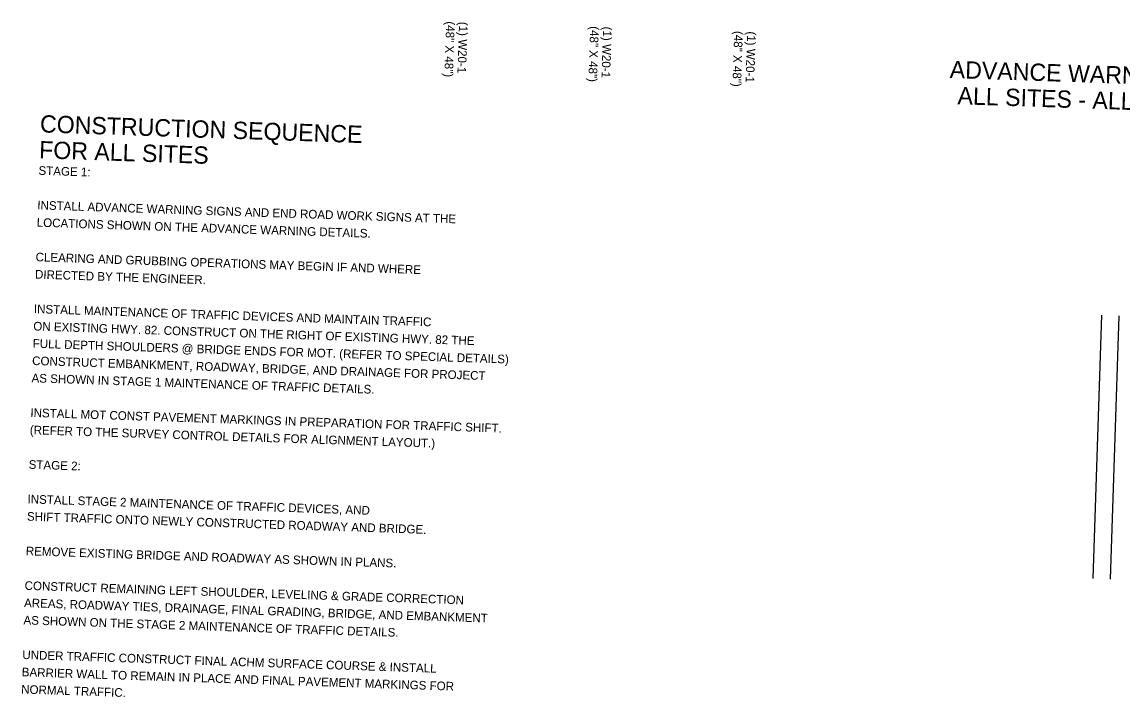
# Model space of a CAD drawing. Extents: x 977269 to 979191, y 1525946 to 1526973.
# Drawn here: x 977311 to 978075, y 1526026 to 1526494 of the extents above; entities that cross this region are included whole.
import ezdxf

# ---------------------------------------------------------------- set-up
doc = ezdxf.new("R2010")
doc.units = 0
doc.layers.add('R_Border', color=7, linetype='Continuous')
doc.layers.add('STAMP', color=7, linetype='Continuous')

msp = doc.modelspace()

# ---------------------------------------------------------------- linework, layer by layer
at = {"layer": 'STAMP'}
for p, q in [((978060.44, 1526290.78), (978054.35, 1526108.19)), ((978072.41, 1526290.39), (978066.32, 1526107.8))]:
    msp.add_line(p, q, dxfattribs=at)

# ---------------------------------------------------------------- texts
at = {"layer": 'R_Border'}
for s, height, rotation, p in [('(48" X 48")', 6, 268.09005, (977605.68, 1526494.7)), ('(1) W20-1', 6, 268.09005, (977614.68, 1526494.4)), ('(48" X 48")', 6, 268.09005, (977705.62, 1526491.37)), ('(1) W20-1', 6, 268.09005, (977714.62, 1526491.07)), ('(48" X 48")', 6, 268.09005, (977805.57, 1526488.04)), ('(1) W20-1', 6, 268.09005, (977814.56, 1526487.74)), ('ADVANCE WARNING DETAILS', 12, 358.09005, (977954.93, 1526455.38)), ('ALL SITES - ALL STAGES', 12, 358.09005, (977960.33, 1526437.19)), ('CONSTRUCTION SEQUENCE ', 12, 358.09005, (977323.76, 1526417.66)), ('FOR ALL SITES', 12, 358.09005, (977323.16, 1526399.67)), ('STAGE 1:', 6, 358.09005, (977322.78, 1526388.23)), ('INSTALL ADVANCE WARNING SIGNS AND END ROAD WORK SIGNS AT THE', 6, 358.09005, (977321.98, 1526364.25)), ('LOCATIONS SHOWN ON THE ADVANCE WARNING DETAILS.  ', 6, 358.09005, (977321.58, 1526352.25)), ('CLEARING AND GRUBBING OPERATIONS MAY BEGIN IF AND WHERE', 6, 358.09005, (977320.78, 1526328.27)), ('DIRECTED BY THE ENGINEER.', 6, 358.09005, (977320.38, 1526316.27)), ('INSTALL MAINTENANCE OF TRAFFIC DEVICES AND MAINTAIN TRAFFIC ', 6, 358.09005, (977319.58, 1526292.29)), ('ON EXISTING HWY. 82. CONSTRUCT ON THE RIGHT OF EXISTING HWY. 82 THE', 6, 358.09005, (977319.18, 1526280.29)), ('FULL DEPTH SHOULDERS @ BRIDGE ENDS FOR MOT. (REFER TO SPECIAL DETAILS)', 6, 358.09005, (977318.78, 1526268.3)), ('CONSTRUCT EMBANKMENT, ROADWAY, BRIDGE, AND DRAINAGE FOR PROJECT ', 6, 358.09005, (977318.38, 1526256.31)), ('AS SHOWN IN STAGE 1 MAINTENANCE OF TRAFFIC DETAILS. ', 6, 358.09005, (977317.98, 1526244.31)), ('INSTALL MOT CONST PAVEMENT MARKINGS IN PREPARATION FOR TRAFFIC SHIFT.', 6, 358.09005, (977317.18, 1526220.33)), ('(REFER TO THE SURVEY CONTROL DETAILS FOR ALIGNMENT LAYOUT.)', 6, 358.09005, (977316.78, 1526208.33)), ('STAGE 2:', 6, 358.09005, (977315.98, 1526184.35)), ('INSTALL STAGE 2 MAINTENANCE OF TRAFFIC DEVICES, AND ', 6, 358.09005, (977315.18, 1526160.36)), ('SHIFT TRAFFIC ONTO NEWLY CONSTRUCTED ROADWAY AND BRIDGE. ', 6, 358.09005, (977314.78, 1526148.37)), ('REMOVE EXISTING BRIDGE AND ROADWAY AS SHOWN IN PLANS.', 6, 358.09005, (977313.98, 1526124.38)), ('CONSTRUCT REMAINING LEFT SHOULDER, LEVELING & GRADE CORRECTION ', 6, 358.09005, (977313.18, 1526100.39)), ('AREAS, ROADWAY TIES, DRAINAGE, FINAL GRADING, BRIDGE, AND EMBANKMENT ', 6, 358.09005, (977312.78, 1526088.4)), ('AS SHOWN ON THE STAGE 2 MAINTENANCE OF TRAFFIC DETAILS.', 6, 358.09005, (977312.38, 1526076.41)), ('UNDER TRAFFIC CONSTRUCT FINAL ACHM SURFACE COURSE & INSTALL', 6, 358.09005, (977311.58, 1526052.42)), ('BARRIER WALL TO REMAIN IN PLACE AND FINAL PAVEMENT MARKINGS FOR', 6, 358.09005, (977311.18, 1526040.43)), ('NORMAL TRAFFIC.', 6, 358.09005, (977310.78, 1526028.43))]:
    msp.add_text(s, height=height, rotation=rotation, dxfattribs=at).set_placement(p)

doc.saveas('drawing.dxf')
